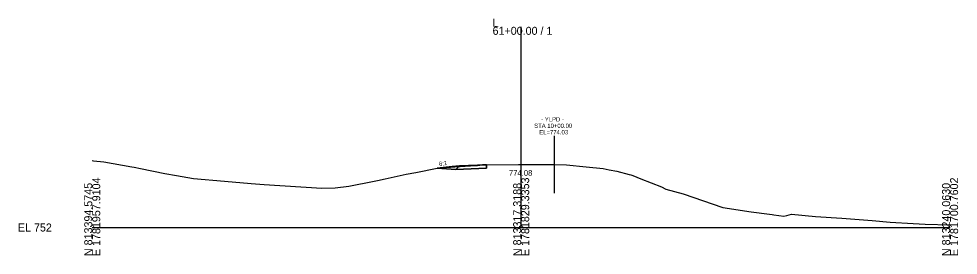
# Model space of a CAD drawing. Extents: x -26 to 7903, y -10 to 9573.
# Drawn here: x 2974.3 to 3302.8, y 1990.3 to 2073 of the extents above; entities that cross this region are included whole.
import ezdxf

# ---------------------------------------------------------------- set-up
doc = ezdxf.new("R2010")
doc.units = 0
for name, color, linetype in [('Exist Cross Section Cell', 7, 'Continuous'), ('Exist XS Center Line Elevation Label', 7, 'Continuous'), ('Exist XS Ground Line', 7, 'Continuous'), ('Prop XS Ditch Slope Text', 7, 'Continuous'), ('Prop XS Earthwork Shape', 7, 'Continuous'), ('Prop XS Finish Grade', 7, 'Continuous'), ('Prop XS Finish Grade Pavement', 7, 'Continuous'), ('Prop XS Pvmt Edge Slope', 7, 'Continuous'), ('Prop XS Subgrade Earthwork', 7, 'Continuous'), ('Prop XS Vertical Lines Alignments', 7, 'Continuous'), ('Scratch_Level_3', 7, 'Continuous'), ('Scratch_Level_6', 7, 'Continuous')]:
    doc.layers.add(name, color=color, linetype=linetype)

msp = doc.modelspace()

# ---------------------------------------------------------------- linework, layer by layer
at = {"layer": 'Exist Cross Section Cell'}
for p, q in [((3150, 2000), (3150, 2070.19)), ((3000, 2000), (3150, 2000)), ((3150, 2000), (3300, 2000))]:
    msp.add_line(p, q, dxfattribs=at)
at = {"layer": 'Exist XS Ground Line'}
for p, q in [((3000, 2023.4), (3000.41, 2023.36)), ((3000.41, 2023.36), (3004.03, 2023.02)), ((3004.03, 2023.02), (3013.82, 2021.24)), ((3013.82, 2021.24), (3014.68, 2021.11)), ((3014.68, 2021.11), (3016.91, 2020.64)), ((3016.91, 2020.64), (3025.43, 2018.85)), ((3113.2, 2019.28), (3120.65, 2020.71)), ((3120.65, 2020.71), (3126.82, 2021.21)), ((3126.82, 2021.21), (3134.2, 2021.7)), ((3134.2, 2021.7), (3134.73, 2021.74)), ((3134.73, 2021.74), (3136.5, 2021.86)), ((3136.5, 2021.86), (3137.92, 2021.95)), ((3137.92, 2021.95), (3149.09, 2022.07)), ((3149.09, 2022.07), (3149.58, 2022.08)), ((3149.58, 2022.08), (3150, 2022.08)), ((3150, 2022.08), (3155.45, 2022.06)), ((3155.45, 2022.06), (3161.49, 2022.03)), ((3161.49, 2022.03), (3165.88, 2021.86)), ((3165.88, 2021.86), (3172.7, 2021.19)), ((3172.7, 2021.19), (3178.69, 2020.61)), ((3178.69, 2020.61), (3180.73, 2020.2)), ((3025.43, 2018.85), (3029.43, 2018.19)), ((3029.43, 2018.19), (3035.41, 2017.17)), ((3102.48, 2017.01), (3109.78, 2018.6)), ((3109.78, 2018.6), (3113.2, 2019.28)), ((3180.73, 2020.2), (3183.47, 2019.66)), ((3183.47, 2019.66), (3187.71, 2018.56)), ((3187.71, 2018.56), (3188.38, 2018.38)), ((3188.38, 2018.38), (3189.05, 2018.15)), ((3189.05, 2018.15), (3191.85, 2017.02)), ((3035.41, 2017.17), (3046.19, 2016.23)), ((3046.19, 2016.23), (3055.58, 2015.4)), ((3055.58, 2015.4), (3060.11, 2015.02)), ((3060.11, 2015.02), (3080.32, 2013.73)), ((3080.32, 2013.73), (3084.9, 2013.92)), ((3084.9, 2013.92), (3089.73, 2014.4)), ((3089.73, 2014.4), (3098.62, 2016.2)), ((3098.62, 2016.2), (3099.8, 2016.43)), ((3099.8, 2016.43), (3102.48, 2017.01)), ((3191.85, 2017.02), (3199.05, 2014.18)), ((3199.05, 2014.18), (3200.6, 2013.4)), ((3200.6, 2013.4), (3206.67, 2011.74)), ((3206.67, 2011.74), (3220.55, 2007.05)), ((3220.55, 2007.05), (3230.44, 2005.47)), ((3230.44, 2005.47), (3236.79, 2004.71)), ((3236.79, 2004.71), (3237.72, 2004.59)), ((3237.72, 2004.59), (3238.36, 2004.48)), ((3238.36, 2004.48), (3241.85, 2003.93)), ((3241.85, 2003.93), (3242.91, 2004.2)), ((3242.91, 2004.2), (3244.53, 2004.61)), ((3244.53, 2004.61), (3252.95, 2003.85)), ((3252.95, 2003.85), (3262.18, 2003.32)), ((3262.18, 2003.32), (3272.73, 2002.47)), ((3272.73, 2002.47), (3279.09, 2001.83)), ((3279.09, 2001.83), (3287.13, 2001.42)), ((3287.13, 2001.42), (3291.23, 2001.13)), ((3291.23, 2001.13), (3300, 2000.96))]:
    msp.add_line(p, q, dxfattribs=at)
at = {"layer": 'Prop XS Earthwork Shape'}
msp.add_lwpolyline([(3137.92, 2020.7), (3127.14, 2020.27), (3120.65, 2020.71), (3126.82, 2021.21), (3134.2, 2021.7), (3134.73, 2021.74), (3136.5, 2021.86), (3137.92, 2021.95)], close=True, dxfattribs=at)
at = {"layer": 'Prop XS Finish Grade'}
for p, q in [((3125.92, 2021.37), (3120.65, 2020.71)), ((3128.44, 2021.57), (3125.92, 2021.37))]:
    msp.add_line(p, q, dxfattribs=at)
at = {"layer": 'Prop XS Finish Grade Pavement'}
msp.add_line((3137.92, 2021.95), (3128.44, 2021.57), dxfattribs=at)
at = {"layer": 'Prop XS Pvmt Edge Slope'}
msp.add_line((3128.44, 2021.57), (3127.14, 2020.27), dxfattribs=at)
at = {"layer": 'Prop XS Subgrade Earthwork'}
for p, q in [((3127.14, 2020.27), (3120.65, 2020.71)), ((3137.92, 2020.7), (3127.14, 2020.27)), ((3137.92, 2020.7), (3137.92, 2021.95))]:
    msp.add_line(p, q, dxfattribs=at)
at = {"layer": 'Prop XS Vertical Lines Alignments'}
msp.add_line((3161.49, 2032.08), (3161.49, 2012.03), dxfattribs=at)
at = {"layer": 'Scratch_Level_3'}
for p, q in [((3125.92, 2021.37), (3120.65, 2020.71)), ((3120.65, 2020.71), (3127.14, 2020.27)), ((3128.44, 2021.57), (3125.92, 2021.37)), ((3127.14, 2020.27), (3128.44, 2021.57))]:
    msp.add_line(p, q, dxfattribs=at)
at = {"layer": 'Scratch_Level_6'}
msp.add_lwpolyline([(3137.92, 2020.7), (3137.92, 2021.95), (3136.5, 2021.86), (3134.73, 2021.74), (3134.2, 2021.7), (3126.82, 2021.21), (3120.65, 2020.71), (3127.14, 2020.27)], close=True, dxfattribs=at)

# ---------------------------------------------------------------- texts
at = {"layer": 'Exist Cross Section Cell'}
for s, p in [('61+00.00 / 1', (3140, 2067.39)), ('L', (3140, 2070.19)), ('EL 752', (2974, 1998.6))]:
    msp.add_text(s, height=2.8, dxfattribs=at).set_placement(p)
for s, p in [('E 1781957.9104', (3002.8, 1990)), ('E 1781829.3353', (3152.8, 1990)), ('E 1781700.7602', (3302.8, 1990)), ('N 813394.5745', (3000, 1990)), ('N 813317.3188', (3150, 1990)), ('N 813240.0630', (3300, 1990))]:
    msp.add_text(s, height=2.8, rotation=90, dxfattribs=at).set_placement(p)
at = {"layer": 'Exist XS Center Line Elevation Label'}
msp.add_text('774.08', height=2, dxfattribs=at).set_placement((3145.73, 2018.08))
at = {"layer": 'Prop XS Ditch Slope Text'}
msp.add_text('6:1', height=1.5, rotation=9.6131, dxfattribs=at).set_placement((3121.38, 2021.44))
at = {"layer": 'Prop XS Vertical Lines Alignments'}
for s, p in [('- YLPD -', (3157, 2037.08)), ('STA 10+00.00', (3154.54, 2034.83)), ('EL=774.03', (3156.34, 2032.58))]:
    msp.add_text(s, height=1.5, dxfattribs=at).set_placement(p)

doc.saveas('drawing.dxf')
